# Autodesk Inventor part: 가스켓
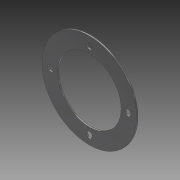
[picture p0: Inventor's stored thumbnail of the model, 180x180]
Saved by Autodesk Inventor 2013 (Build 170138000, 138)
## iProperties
Created: 2024-02
Part Number: 가스켓
Material: 스테인리스강
Document SubType Name: Modeling
Designer: mdu-01
Density: 1 g/cm^3
Author: mdu-01
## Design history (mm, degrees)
sketch "스케치1"
  geometry: C1 r 35 at (0, 0); C2 r 23.5 at (0, 0); C3 r 2.25 at (0, 28.5); C4 r 2.25 at (28.5, 0); C5 r 2.25 at (-28.5, 0); C6 r 2.25 at (0, -28.5); A1 r 28.5 centre (0, 0) between (0, 28.5) and (28.5, 0); 1 further point
  constraints: 7 centre point, 4 point on circle, 3 coincident, 3 equal radius, 2 horizontal alignment, 2 vertical alignment
  dimensions: "d0" = 70 diameter of C1; "d1" = 47 diameter of C2; "d2" = 57 diameter of A1; "d3" = 4.5 diameter of C3
extrude "돌출1" new body sketch "스케치1" distance "d4" = 1; taper "d5" = 0 deg
node "솔리드1"
